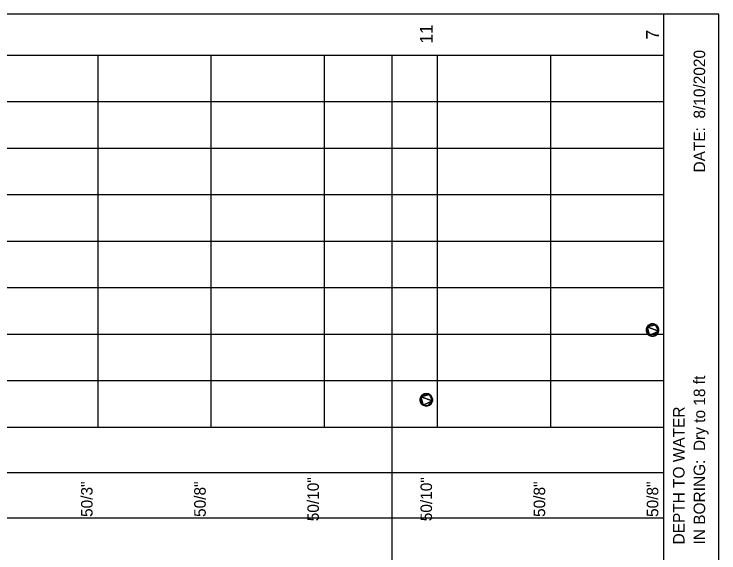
# Model space of a CAD drawing. Extents: x 1313964 to 1316843, y 2087046 to 2096619.
# Drawn here: x 1314005.66 to 1314036.8, y 2089892.52 to 2089916.31 of the extents above; entities that cross this region are included whole.
import ezdxf

# ---------------------------------------------------------------- set-up
doc = ezdxf.new("R2010")
doc.units = 0
doc.layers.add('B-Sub-Contour', color=7, linetype='Continuous')
doc.layers.add('Default', color=7, linetype='Continuous')

# ---------------------------------------------------------------- blocks, each defined once
blk = doc.blocks.new('POINT_DISPLAY')
at = {"layer": 'Default'}
blk.add_line((0, 0), (0, 0), dxfattribs=at)
blk = doc.blocks.new('DMK_101')
at = {"layer": 'Default'}
for points in [[(-14269.212, 2386.584), (-14476.476, 0), (-14269.212, -2386.584), (-14269.212, 2386.584)], [(-12638.532, 6858), (-13653.516, 4690.872), (-14269.212, 2386.584), (-12638.532, 6858)], [(-12638.532, 6858), (-14269.212, 2386.584), (-14269.212, -2386.584), (-12638.532, 6858)], [(-12638.532, 6858), (-14269.212, -2386.584), (-3147.06, -13508.736), (-12638.532, 6858)], [(-3147.06, 13511.784), (-7618.476, 11878.056), (-12638.532, 6858), (-3147.06, 13511.784)], [(6097.524, 11878.056), (-3147.06, 13511.784), (-12638.532, 6858), (6097.524, 11878.056)], [(-7618.476, 11878.056), (-11266.932, 8820.912), (-12638.532, 6858), (-7618.476, 11878.056)], [(-3147.06, -13508.736), (6097.524, 11878.056), (-12638.532, 6858), (-3147.06, -13508.736)], [(-7618.476, 11878.056), (-9578.34, 10506.456), (-11266.932, 8820.912), (-7618.476, 11878.056)], [(-9578.34, 10506.456), (-10456.164, 9698.736), (-11266.932, 8820.912), (-9578.34, 10506.456)], [(-3147.06, 13511.784), (-5451.348, 12893.04), (-7618.476, 11878.056), (-3147.06, 13511.784)], [(1626.108, 13511.784), (-760.476, 13712.952), (-3147.06, 13511.784), (1626.108, 13511.784)], [(6097.524, 11878.056), (1626.108, 13511.784), (-3147.06, 13511.784), (6097.524, 11878.056)], [(-3147.06, -13508.736), (11117.58, -6858), (6097.524, 11878.056), (-3147.06, -13508.736)], [(6097.524, 11878.056), (3930.396, 12893.04), (1626.108, 13511.784), (6097.524, 11878.056)], [(11117.58, 6858), (8060.436, 10506.456), (6097.524, 11878.056), (11117.58, 6858)], [(12751.308, 2386.584), (11117.58, 6858), (6097.524, 11878.056), (12751.308, 2386.584)], [(11117.58, -6858), (12751.308, 2386.584), (6097.524, 11878.056), (11117.58, -6858)], [(9745.98, 8820.912), (8938.26, 9698.736), (8060.436, 10506.456), (9745.98, 8820.912)], [(11117.58, 6858), (9745.98, 8820.912), (8060.436, 10506.456), (11117.58, 6858)], [(12751.308, 2386.584), (12132.564, 4690.872), (11117.58, 6858), (12751.308, 2386.584)], [(11117.58, -6858), (12751.308, -2386.584), (12751.308, 2386.584), (11117.58, -6858)], [(12751.308, -2386.584), (12952.476, 0), (12751.308, 2386.584), (12751.308, -2386.584)], [(-14269.212, -2386.584), (-13653.516, -4690.872), (-12638.532, -6858), (-14269.212, -2386.584)], [(-14269.212, -2386.584), (-12638.532, -6858), (-9578.34, -10506.456), (-14269.212, -2386.584)], [(-14269.212, -2386.584), (-9578.34, -10506.456), (-3147.06, -13508.736), (-14269.212, -2386.584)], [(-12638.532, -6858), (-11266.932, -8817.864), (-9578.34, -10506.456), (-12638.532, -6858)], [(-11266.932, -8817.864), (-10456.164, -9695.688), (-9578.34, -10506.456), (-11266.932, -8817.864)], [(-9578.34, -10506.456), (-7618.476, -11878.056), (-3147.06, -13508.736), (-9578.34, -10506.456)], [(-7618.476, -11878.056), (-5451.348, -12893.04), (-3147.06, -13508.736), (-7618.476, -11878.056)], [(-3147.06, -13508.736), (6097.524, -11878.056), (11117.58, -6858), (-3147.06, -13508.736)], [(-3147.06, -13508.736), (1626.108, -13508.736), (6097.524, -11878.056), (-3147.06, -13508.736)], [(-3147.06, -13508.736), (-760.476, -13716), (1626.108, -13508.736), (-3147.06, -13508.736)], [(1626.108, -13508.736), (3930.396, -12893.04), (6097.524, -11878.056), (1626.108, -13508.736)], [(6097.524, -11878.056), (8060.436, -10506.456), (11117.58, -6858), (6097.524, -11878.056)], [(8060.436, -10506.456), (9745.98, -8817.864), (11117.58, -6858), (8060.436, -10506.456)], [(8060.436, -10506.456), (8938.26, -9695.688), (9745.98, -8817.864), (8060.436, -10506.456)], [(11117.58, -6858), (12132.564, -4690.872), (12751.308, -2386.584), (11117.58, -6858)]]:
    blk.add_lwpolyline(points, close=True, dxfattribs=at)
blk.add_blockref('POINT_DISPLAY', (14479.524, 0), dxfattribs=at)

msp = doc.modelspace()

# ---------------------------------------------------------------- linework, layer by layer
at = {"layer": 'B-Sub-Contour'}
for points in [[(1314036.804, 2089873.434), (1314036.804, 2089916.306), (1313975.385, 2089916.306), (1313975.385, 2089873.434), (1314036.804, 2089873.434)], [(1314034.372, 2089873.434), (1314034.372, 2089916.306)], [(1314034.372, 2089914.481), (1313982.683, 2089914.481)], [(1314034.372, 2089914.481), (1313989.372, 2089914.481)], [(1314009.372, 2089898.063), (1314009.372, 2089914.481)], [(1314014.372, 2089898.063), (1314014.372, 2089914.481)], [(1314019.372, 2089898.063), (1314019.372, 2089914.481)], [(1314022.372, 2089894.049), (1314022.372, 2089914.481)], [(1314024.372, 2089898.063), (1314024.372, 2089914.481)], [(1314029.372, 2089898.063), (1314029.372, 2089914.481)], [(1314034.372, 2089898.063), (1314034.372, 2089914.481)], [(1314034.372, 2089912.429), (1313989.372, 2089912.429)], [(1314034.372, 2089910.377), (1313989.372, 2089910.377)], [(1314034.372, 2089908.324), (1313989.372, 2089908.324)], [(1314034.372, 2089906.272), (1313989.372, 2089906.272)], [(1314034.372, 2089904.22), (1313989.372, 2089904.22)], [(1314034.372, 2089902.167), (1313989.372, 2089902.167)], [(1314034.372, 2089900.115), (1313989.372, 2089900.115)], [(1314034.372, 2089898.063), (1313982.683, 2089898.063)], [(1314034.372, 2089898.063), (1313989.372, 2089898.063)], [(1314034.372, 2089896.056), (1313982.683, 2089896.056)], [(1314034.372, 2089894.049), (1313982.683, 2089894.049)], [(1314022.372, 2089878.178), (1314022.372, 2089894.049)]]:
    msp.add_lwpolyline(points, dxfattribs=at)

# ---------------------------------------------------------------- block references
at = {"layer": 'B-Sub-Contour', "xscale": 1.9951013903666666e-05, "yscale": 1.9951013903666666e-05, "rotation": 90}
for p in [(1314033.872, 2089902.373), (1314033.872, 2089902.373), (1314023.872, 2089899.294), (1314023.872, 2089899.294)]:
    msp.add_blockref('DMK_101', p, dxfattribs=at)

# ---------------------------------------------------------------- texts
at = {"layer": 'B-Sub-Contour'}
for s, height, p in [('11', 0.5655, (1314024.154, 2089915.008)), ('7', 0.566, (1314034.154, 2089915.187)), ('DATE:  8/10/2020', 0.50899, (1314036.196, 2089909.313)), ('IN BORING:  Dry to 18 ft', 0.50899, (1314036.196, 2089892.894)), ('DEPTH TO WATER', 0.50899, (1314035.284, 2089892.894)), ('50/10"', 0.509, (1314019.126, 2089893.918)), ('50/10"', 0.509, (1314024.126, 2089893.918)), ('50/3"', 0.509, (1314009.126, 2089894.107)), ('50/8"', 0.509, (1314014.126, 2089894.107)), ('50/8"', 0.509, (1314029.126, 2089894.107)), ('50/8"', 0.509, (1314034.126, 2089894.107))]:
    msp.add_text(s, height=height, rotation=90, dxfattribs=at).set_placement(p)

doc.saveas('drawing.dxf')
